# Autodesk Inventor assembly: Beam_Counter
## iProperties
Shininess: 64.0
Length Units: 11269
Angle Units: 11279
Time Units: 11290
Mass Units: 11283
Length Display Precision: 3
Angle Display Precision: 2
Compacted: True
Created: 2003-02
Part Number: Beam_Counter
Document SubType Name: Assembly
Designer: hofer_a
Density: 0.0
Volumn: 0.0
Area: 0.0
PropertySet Name: Model Information
Control State: 0
Master: False
Checked Out: False
Author: hofer_a
